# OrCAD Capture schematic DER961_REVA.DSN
size D; rev: A
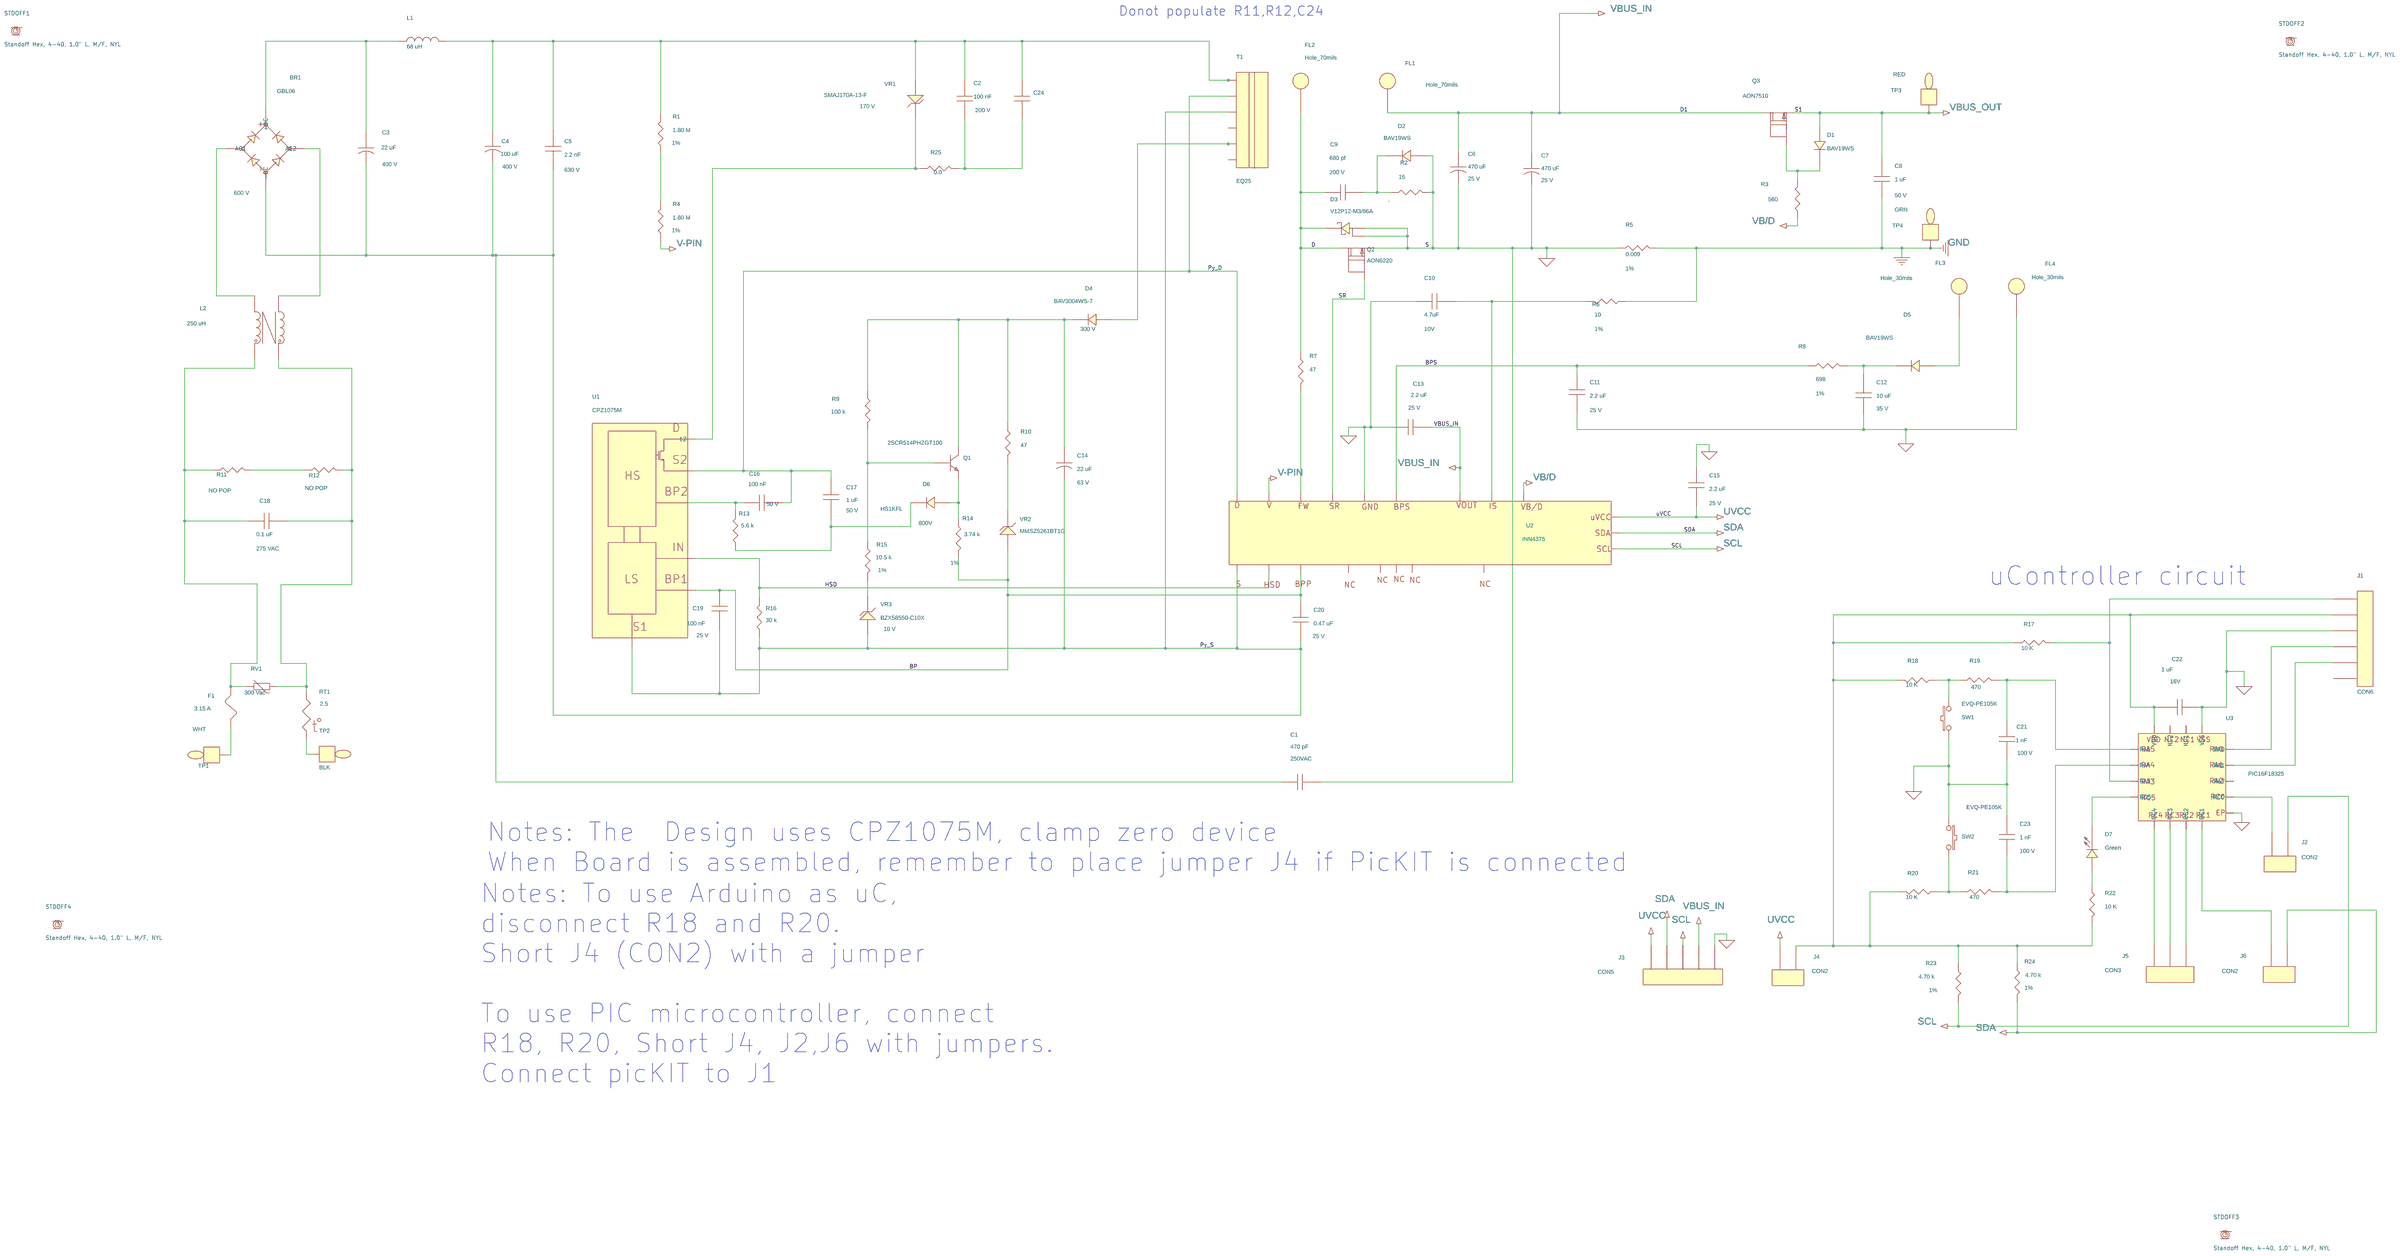
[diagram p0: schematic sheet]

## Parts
BR1  GBL06  [pidaxbridgegbl06]
C1  470 pF  [pinpcapraD7mmxLS10mm030]
C2  100 nF  [pismc1206]
C3  22 uF  [pipolcapclyd320ls140030]
C4  100 uF  [pipolcapclyd630ls300040]
C5  2.2 nF  [pismc1206]
C6  470 uF  [pipolcapcyld400ls200040]
C7  470 uF  [pipolcapcyld400ls200040]
C8  1 uF  [pismc0805]
C9  680 pf  [pismc0805]
C10  4.7uF  [pismc0603]
C11  2.2 uF  [pismc0805]
C12  10 uF  [pismc0805]
C13  2.2 uF  [pismc0805]
C14  22 uF  [pipolcapclyd200ls80030]
C15  2.2 uF  [pismc0603]
C16  100 nF  [pismc0603]
C17  1 uF  [pismc0805]
C18  0.1 uF  [pinpxcaprad5x13x11p1mm040]
C19  100 nF  [pismc0603]
C20  0.47 uF  [pismc0805]
C21  1 nF  [pismr0402]
C22  1 uF  [pismr0402]
C23  1 nF  [pismr0402]
C24  100 nF  [pismc1206]
D1  BAV19WS  [pismsod323]
D2  BAV19WS  [pismsod323]
D3  V12P12-M3/86A  [pi_sm_d_to-277a]
D4  BAV3004WS-7  [pismsod323]
D5  BAV19WS  [pismsod323]
D6  HS1KFL  [pi_sm_sod-123_12]
D7  Green  [pi_sm_d_0603]
F1  3.15 A  [pi_rst_microfuse]
FL1  Hole_70mils  [pi_hole_70mil]
FL2  Hole_70mils  [pi_hole_70mil]
FL3  Hole_30mils  [pi_hole_30mil]
FL4  Hole_30mils  [pi_hole_30mil]
J1  CON6  [pi_molex_06_ra_22series]
J2  CON2  [pimolex2kkheader]
J3  CON5  [PI_HDRF_1X5_Hirose]
J4  CON2  [pimolex2kkheader]
J5  CON3  [pi_molex_3_100_header]
J6  CON2  [pimolex2kkheader]
L1  68 uH  [pi2p14Dx6mmWd060]
L2  250 uH  [pi_toroid_CMC4p_V_275uH]
Q1  2SCR514PHZGT100  [pismsot89123]
Q2  AON6220  [pismpqfn5x6b]
Q3  AON7510  [pism8dfn_ep3p3x3p3a]
R1  1.80 M  [pismr1206]
R2  15  [pismr1206]
R3  560  [pismr0603]
R4  1.80 M  [pismr1206]
R5  0.009  [pismr0805]
R6  10  [pismr0603]
R7  47  [pismr0603]
R8  698  [pismr1206]
R9  100 k  [pismr0603]
R10  47  [pismr0603]
R11  NO POP  [pismr1206]
R12  NO POP  [pismr1206]
R13  5.6 k  [pismr0603]
R14  3.74 k  [pismr0603]
R15  10.5 k  [pismr0603]
R16  30 k  [pismr0402]
R17  10 K  [pismr0402]
R18  10 K  [pismr0402]
R19  470  [pismr0402]
R20  10 K  [pismr0402]
R21  470  [pismr0402]
R22  10 K  [pismr0402]
R23  4.70 k  [pismr0402]
R24  4.70 k  [pismr0402]
R25  0.0  [pismr0805]
RT1  2.5  [pi_rad150x300ls200d030]
RV1  300 Vac  [pidisc350x225ls240x140040]
STDOFF1  Standoff Hex, 4-40, 1.0" L, M/F, NYL
STDOFF2  Standoff Hex, 4-40, 1.0" L, M/F, NYL
STDOFF3  Standoff Hex, 4-40, 1.0" L, M/F, NYL
STDOFF4  Standoff Hex, 4-40, 1.0" L, M/F, NYL
SW1  EVQ-PE105K  [pi_switch_spst_smd_1]
SW2  EVQ-PE105K  [pi_switch_spst_smd_1]
T1  EQ25  [pi_bobbin_eq-25_6p]
TP1  WHT  [pitpkeystone125x125]
TP2  BLK  [pitpkeystone125x125]
TP3  RED  [pitpkeystone125x125]
TP4  GRN  [pitpkeystone125x125]
U1  CPZ1075M  [PI_SM_MinSOP16A_1]
U2  INN4375  [inSOP-T28D]
U3  PIC16F18325  [pi_sm_16_uQFN_EP]
VR1  SMAJ170A-13-F  [pismdo214ac12]
VR2  MMSZ5261BT1G  [pi_sm_sod-123_12]
VR3  BZX58550-C10X  [pismdsod52312]

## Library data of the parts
BR1 = DISCRETE_BRIDGE_+~~-: Disp_Voltage: 600 V; Part Number: 15-01112-00; ROOM: 1
C1 = CAP_NP: COMPGROUP: 3; Disp_Voltage: 250VAC; PCB Editor PCBFP: pinpycaprad540x290ls400040; Part Number: 20-01454-00; ROOM: 3; Voltage: 250VAC
C2 C24 = CAP_NP: Disp_Voltage: 200 V; Part Number: 20-00918-00; ROOM: 2; Voltage: 200 V
C3 = CAP_POL: ALT_SYMBOLS: pipolcapclyd320ls140030h630; Disp_Voltage: 400 V; FPLIST: pipolcapclyd320ls140030,pipolcapclyd320ls140030430h,pipolcapclyd320ls140030h630; Part Number: 20-01315-00; Voltage: 400 V
C4 = CAP_POL: ALT_SYMBOLS: pipolcapclyd630ls3000401120h; COMPGROUP: 1; Disp_Voltage: 400 V; FPLIST: pipolcapclyd630ls300040,pipolcapclyd630ls3000401120h; Part Number: 20-00517-00; Voltage: 400 V
C5 = CAP_NP: Disp_Voltage: 630 V; Part Number: 20-08609-00; ROOM: 1; Voltage: 630 V
C6 C7 = CAP_POL: Disp_Voltage: 25 V; Part Number: 20-09056-00; ROOM: 3; Voltage: 25 V
C8 = CAP_NP: Disp_Voltage: 50 V; Part Number: 20-00853-00; ROOM: 3; Voltage: 50 V
C9 = CAP_NP: Disp_Voltage: 200 V; Part Number: 24-00025-00; Voltage: 200 V
C10 = CAP_NP: Disp_Voltage: 10V; Part Number: 20-09016-00; ROOM: 3; Voltage: 10 V
C11 C13 = CAP_NP: Disp_Voltage: 25 V; Part Number: 20-01594-00; Voltage: 25 V
C12 = CAP_NP: ALT_SYMBOLS: pismc0805_1; Disp_Voltage: 35 V; FPLIST: pismc0805,pismc0805_1; Part Number: 20-01692-00; ROOM: 3; Voltage: 35 V
C14 = CAP_POL: ALT_SYMBOLS: pipolcapclyd5p0x12p5ls2p0d30h; Disp_Voltage: 63 V; FPLIST: pipolcapclyd200ls80030,pipolcapclyd5p0x12p5ls2p0d30h; Part Number: 20-09168-00; ROOM: 2; Voltage: 63 V
C15 = CAP_NP: ALT_SYMBOLS: pismc0603_1; Disp_Voltage: 25 V; FPLIST: pismc0603,pismc0603_1; Part Number: 20-09023-00; Voltage: 25 V
C16 = CAP_NP: Disp_Voltage: 50 V; Part Number: 20-01693-00; ROOM: 2; Voltage: 50 V
C17 = CAP_NP: Disp_Voltage: 50 V; Part Number: 20-00853-00; ROOM: 2; Voltage: 50 V
C18 = CAP_NP: ALT_SYMBOLS: pinpxcaprad5x13x11p1mm040h; Disp_Voltage: 275 VAC; FPLIST: pinpxcaprad5x13x11p1mm040,pinpxcaprad5x13x11p1mm040h; Part Number: 20-09109-00; ROOM: 1; Voltage: 275 VAC
C19 = CAP_NP: Disp_Voltage: 25 V; Part Number: 20-00528-00; ROOM: 2; Voltage: 25 V
C20 = CAP_NP: Disp_Voltage: 25 V; Part Number: 20-09182-00; ROOM: 3; Voltage: 25 V
C21 C23 = CAP_NP: ALT_SYMBOLS: pismr0402_1; Disp_Voltage: 100 V; FPLIST: pismr0402,pismr0402_1; Part Number: 20-00843-00; Voltage: 100 V
C22 = CAP_NP: ALT_SYMBOLS: cc0402; Disp_Voltage: 16V; FPLIST: pismr0402,cc0402; Part Number: 20-01373-00; Voltage: 16V
D1 D5 = DIODE: COMPGROUP: 1; Part Number: 15-00658-00; ROOM: 3
D2 = DIODE: Part Number: 15-00658-00; ROOM: 3
D3 = DIODE_SCHOTTKY_TO-277A: Part Number: 15-01194-00; ROOM: 3
D4 = DIODE: COMPGROUP: 1; Disp_Voltage: 300 V; Part Number: 15-01138-00; ROOM: 2
D6 = DIODE: COMPGROUP: 2; Disp_Voltage: 800V; Part Number: 15-01686-00; ROOM: 2
D7 = LED: Part Number: 15-00955-00
F1 = FUSE: ALT_SYMBOLS: pirstmicrofusehoz; COMPGROUP: 1; FPLIST: pi_rst_microfuse,pirstmicrofusehoz; Part Number: 40-00020-00; ROOM: 1
FL1 FL2 = FlyingLead: Part Number: 35-00282-00; ROOM: 3
FL3 FL4 = FlyingLead: Part Number: 35-00284-00; ROOM: 3
J1 = CON6: Part Number: 35-00226-00
J2 J4 J6 = CON2: Part Number: 35-00077-00
J3 = CON5: Part Number: 35-00428-00
J5 = CON3: Part Number: 35-00091-00
L1 = INDUCTOR: Part Number: 32-00411-00
L2 = TORRID_4P_12_34: ALT_SYMBOLS: pi_toroid_CMC4p_V,pi_toroid_CMC4p_V_275uH; FPLIST: pi_toroid_CMC4p_H,pi_toroid_CMC4p_V,pi_toroid_CMC4p_V_275uH; Part Number: 32-00367-00; ROOM: 1
Q1 = NPN_BCE: Part Number: 55-00175-00
Q2 = FET_N_SGD_123_4_5678: Part Number: 50-00276-00; ROOM: 3
Q3 = FET_N_SGD_123_4_1: Part Number: 50-00297-00; ROOM: 3
R1 R4 = R: Disp_Tol: 1%; Part Number: 05-03155-00
R2 = R: Part Number: 05-01308-00
R3 = R: Part Number: 05-01682-00; ROOM: 3
R5 = R: Disp_Tol: 1%; Part Number: 05-06508-00; ROOM: 3
R6 = R: Disp_Tol: 1%; Part Number: 05-00886-00
R7 = R: Part Number: 05-01656-00; ROOM: 3
R8 = R: Disp_Tol: 1%; Part Number: 05-00178-00; ROOM: 3
R9 = R: Part Number: 05-01736-00; ROOM: 2
R10 = R: Part Number: 05-01656-00; ROOM: 2
R11 R12 = R: Part Number: 05-01428-00; ROOM: 1
R13 = R: Part Number: 05-01706-00; ROOM: 2
R14 = R: Disp_Tol: 1%; Part Number: 05-01133-00; ROOM: 2
R15 = R: Disp_Tol: 1%; Part Number: 05-03184-00
R16 = R: Part Number: 05-06246-00; ROOM: 2
R17 R18 R20 R22 = R: Part Number: 05-03488-00
R19 R21 = R: Part Number: 05-06207-00
R23 R24 = R: Disp_Tol: 1%; Part Number: 05-05899-00
R25 = R: ALT_SYMBOLS: pismr0805_1; FPLIST: pismr0805,pismr0805_1; Part Number: 05-03159-00; ROOM: 3
RT1 = THERMISTOR: ALT_SYMBOLS: pirad400x300ls200040_h; FPLIST: pi_rad150x300ls200d030,pirad400x300ls200040_h; Part Number: 90-00040-00
RV1 = VARISTOR: Part Number: 85-00031-00
STDOFF1-STDOFF4 = STDOFF_HEX_4-40: Part Number: 76-00021-00
SW1 SW2 = SW_PUSHBUTTON: Part Number: 66-00190-00
T1 = BEQ25_6P: Part Number: 25-01136-00
TP1 = TESTPOINT: Part Number: 35-00044-00
TP2 = TESTPOINT: Part Number: 35-00042-00
TP3 = TESTPOINT: Part Number: 35-00043-00
TP4 = TESTPOINT: Part Number: 35-00187-00
U1 = ClampZeroMinSOP16: Part Number: 10-01330-00; ROOM: 2
U2 = DEV_INN4375: Part Number: 10-01269-00; ROOM: 3
U3 = PIC16F18325-I_JQ: Part Number: 45-00476-00
VR1 = DIODE_ZENER: Disp_Voltage: 170 V; Part Number: 15-01702-00; ROOM: 2
VR2 = DIODE_ZENER: Part Number: 15-01102-00; ROOM: 2
VR3 = DIODE_ZENER: ALT_SYMBOLS: pi_sm_d_ssmini2p; Disp_Voltage: 10 V; FPLIST: pismdsod52312,pi_sm_d_ssmini2p; Part Number: 16-00010-00

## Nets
GND_SIGNAL: C1.2 C6.2 C7.2 C10.1 C11.2 C12.1 C13.1 C15.1 C21.2 C22.1 C23.2 D2.2 D3.1(A1) D3.2(A2) FL4.1 J1.3 J3.1 Q2.1(S) Q2.2(S) Q2.3(S) R2.1 R5.1 SW1.2 SW2.2 U2.2 U3.13(VSS) U3.EP
BP: C19.1 C20.1 R14.2 U1.8 U2.17 VR2.2
BPS: C11.1 R8.1 U2.4
D: C9.1 D3.3(Cathode) FL2.1 Q2.5(D) Q2.6(D) Q2.7(D) Q2.8(D) R7.1
D1: C6.1 C7.1 C13.2 FL1.1 J3.2 Q3.5(D1) Q3.6(D1) Q3.7(D1) Q3.8(D1) U2.10
HSD: R16.2 U1.7 U2.18
Py_D: C16.2 C17.1 T1.2 U1.10 U2.28
Py_S: BR1.4(-DC) C1.1 C3.2 C4.2 C5.2 C14.2 C19.2 C20.2 R16.1 T1.3 U1.3 U2.19 VR3.2
RTN: C8.1 R5.2 R6.1 TP4.1
S1: C8.2 D1.2 Q3.1(S1) Q3.2(S1) Q3.3(S1) TP3.1
SCL: J2.1 J3.3 R23.2 U2.5
SDA: J3.4 J6.1 R24.2 U2.6
SR: Q2.4(G) U2.9
uVcc: C15.2 J3.5 J4.1 U2.7
V-PIN: R4.1 U2.15
VB/D: R3.1 U2.8
N12382100: C9.2 D2.1 R2.2
N12382458: C14.1 D4.1 Q1.2(COLLECTOR) R9.1 R10.1
N12382462: D4.2 T1.5
N12382746: Q1.1(BASE) R9.2 R15.1
N12382804: R25.1 U1.16(12) VR1.1
N12382856: R10.2 VR2.1
N12382926: C16.1 R13.2 U1.9
N12382930: D6.2 Q1.3(EMITTER) R14.1
N12383060: C17.2 D6.1 R13.1
N12396349: BR1.1(+DC) C3.1 L1.1
N12396391: BR1.3(AC2) L2.4
N12396649: C18.1 F1.2 L2.1 R11.1 RV1.1
N12396657: R11.2 R12.1
N12396665: C18.2 L2.3 R12.2 RT1.1 RV1.2
N12396815: F1.1 TP1.1
N12398163: R1.1 R4.2
N12503104: C12.2 D5.1 R8.2
N12503149: D5.2 FL3.1
N12504243: D1.1 Q3.4(G) R3.2
N12596211: R7.2 U2.11
N12608133: C10.2 R6.2 U2.1
N12703783: C2.1 C4.1 C5.1 C24.1 L1.2 R1.2 T1.1 VR1.2
N12708941: RT1.2 TP2.1
N12714135: C2.2 C24.2 R25.2
N12716573: BR1.2(AC1) L2.2
N12772840: R15.2 VR3.1
N12794080: J1.1 R17.1 U3.3(RA3)
N12794088: C22.2 J1.2 J4.2 R17.2 R18.2 R20.2 R22.2 R23.1 R24.1 U3.16(VDD)
N12794144: J1.4 U3.12(RAO)
N12794152: J1.5 U3.11(RA1)
N12794212: R18.1 R19.1 SW1.1
N12794224: C21.1 R19.2 U3.1(RA5)
N12794382: C23.1 R21.2 U3.2(RA4)
N12794426: D7.1(CATHODE) U3.4(RC5)
N12794434: J2.2 U3.9(RC0)
N12794496: J5.3 U3.5(RC4)
N12794500: J5.2 U3.6(RC3)
N12794504: J5.1 U3.7(RC2)
N12794508: J6.2 U3.8(RC1)
N12794532: R20.1 R21.1 SW2.1
N12794554: D7.2(ANODE) R22.1

Not connected (* = marked no-connect by the designer): J1 6; T1 4 6; U1 1 2 4 5 6 11; U2 3 12 13 14 16; U3 10(RA2) 14(NC1) 15(NC2)

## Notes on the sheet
- Donot populate R11,R12,C24
- uController circuit
- Notes: The  Design uses CPZ1075M, clamp zero device
  When Board is assembled, remember to place jumper J4 if PicKIT is connected
- Notes: To use Arduino as uC,
  disconnect R18 and R20.
  Short J4 (CON2) with a jumper
  To use PIC microcontroller, connect
  R18, R20, Short J4, J2,J6 with jumpers.
  Connect picKIT to J1
